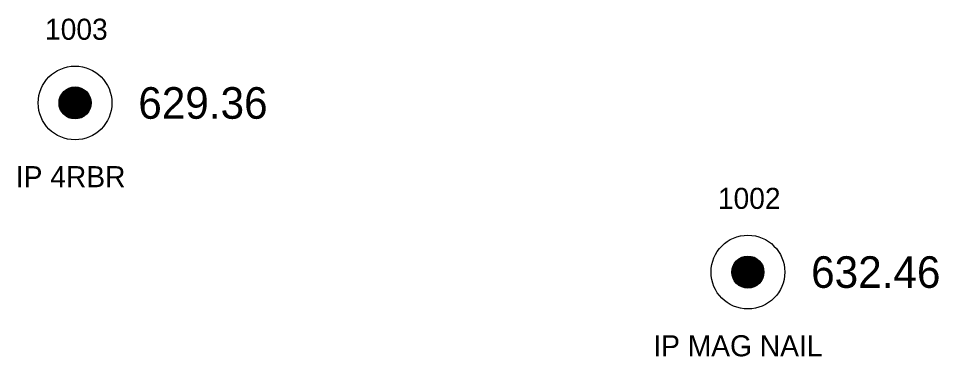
# Model space of a CAD drawing. Extents: x 1694813 to 1696862, y 1086485 to 1091027.
# Drawn here: x 1695770.52 to 1695814.17, y 1087216.3 to 1087232.36 of the extents above; entities that cross this region are included whole.
import ezdxf

# ---------------------------------------------------------------- set-up
doc = ezdxf.new("R2010")
doc.units = 0
for name, color, linetype in [('RD_EX_DV_Prop_txCode', 7, 'Continuous'), ('RD_EX_DV_PropPin', 7, 'Continuous'), ('RD_EX_TX_DV_Prop_ELEV', 7, 'Continuous'), ('RD_SMD_Locator', 7, 'Continuous')]:
    doc.layers.add(name, color=color, linetype=linetype)

msp = doc.modelspace()

# ---------------------------------------------------------------- linework, layer by layer
at = {"layer": 'RD_EX_DV_PropPin'}
for p, q in [((1695772.715, 1087227.762), (1695772.715, 1087228.927)), ((1695772.75, 1087227.735), (1695772.75, 1087228.954)), ((1695772.785, 1087227.71), (1695772.785, 1087228.979)), ((1695772.82, 1087227.688), (1695772.82, 1087229.001)), ((1695772.855, 1087227.669), (1695772.855, 1087229.02)), ((1695772.89, 1087227.652), (1695772.89, 1087229.037)), ((1695772.925, 1087227.637), (1695772.925, 1087229.052)), ((1695772.96, 1087227.624), (1695772.96, 1087229.065)), ((1695772.995, 1087227.613), (1695772.995, 1087229.076)), ((1695773.03, 1087227.604), (1695773.03, 1087229.085)), ((1695773.065, 1087227.596), (1695773.065, 1087229.093)), ((1695773.1, 1087227.591), (1695773.1, 1087229.098)), ((1695773.135, 1087227.587), (1695773.135, 1087229.102)), ((1695773.17, 1087227.584), (1695773.17, 1087229.105)), ((1695773.205, 1087227.583), (1695773.205, 1087229.106)), ((1695773.24, 1087227.584), (1695773.24, 1087229.105)), ((1695773.275, 1087227.587), (1695773.275, 1087229.102)), ((1695773.31, 1087227.591), (1695773.31, 1087229.098)), ((1695773.345, 1087227.596), (1695773.345, 1087229.093)), ((1695773.38, 1087227.604), (1695773.38, 1087229.085)), ((1695773.415, 1087227.613), (1695773.415, 1087229.076)), ((1695773.45, 1087227.624), (1695773.45, 1087229.065)), ((1695773.485, 1087227.637), (1695773.485, 1087229.052)), ((1695773.52, 1087227.652), (1695773.52, 1087229.037)), ((1695773.555, 1087227.669), (1695773.555, 1087229.02)), ((1695773.59, 1087227.688), (1695773.59, 1087229.001)), ((1695773.625, 1087227.71), (1695773.625, 1087228.979)), ((1695773.66, 1087227.735), (1695773.66, 1087228.954)), ((1695773.695, 1087227.762), (1695773.695, 1087228.927)), ((1695772.47, 1087228.148), (1695772.47, 1087228.541)), ((1695772.505, 1087228.047), (1695772.505, 1087228.642)), ((1695772.54, 1087227.975), (1695772.54, 1087228.714)), ((1695772.575, 1087227.918), (1695772.575, 1087228.771)), ((1695772.61, 1087227.87), (1695772.61, 1087228.819)), ((1695772.645, 1087227.829), (1695772.645, 1087228.86)), ((1695772.68, 1087227.794), (1695772.68, 1087228.895)), ((1695773.73, 1087227.794), (1695773.73, 1087228.895)), ((1695773.766, 1087227.829), (1695773.766, 1087228.86)), ((1695773.801, 1087227.87), (1695773.801, 1087228.819)), ((1695773.836, 1087227.918), (1695773.836, 1087228.771)), ((1695773.871, 1087227.975), (1695773.871, 1087228.714)), ((1695773.906, 1087228.047), (1695773.906, 1087228.642)), ((1695773.941, 1087228.148), (1695773.941, 1087228.541)), ((1695804.953, 1087219.575), (1695804.953, 1087221.056)), ((1695804.988, 1087219.567), (1695804.988, 1087221.063)), ((1695805.023, 1087219.562), (1695805.023, 1087221.069)), ((1695805.058, 1087219.558), (1695805.058, 1087221.073)), ((1695805.093, 1087219.555), (1695805.093, 1087221.076)), ((1695805.128, 1087219.554), (1695805.128, 1087221.076)), ((1695805.163, 1087219.555), (1695805.163, 1087221.076)), ((1695805.198, 1087219.558), (1695805.198, 1087221.073)), ((1695805.233, 1087219.562), (1695805.233, 1087221.069)), ((1695805.268, 1087219.567), (1695805.268, 1087221.063)), ((1695805.303, 1087219.575), (1695805.303, 1087221.056)), ((1695804.427, 1087220.017), (1695804.427, 1087220.613)), ((1695804.463, 1087219.946), (1695804.463, 1087220.685)), ((1695804.498, 1087219.889), (1695804.498, 1087220.742)), ((1695804.533, 1087219.841), (1695804.533, 1087220.789)), ((1695804.568, 1087219.8), (1695804.568, 1087220.83)), ((1695804.603, 1087219.765), (1695804.603, 1087220.866)), ((1695804.638, 1087219.733), (1695804.638, 1087220.897)), ((1695804.673, 1087219.705), (1695804.673, 1087220.925)), ((1695804.708, 1087219.681), (1695804.708, 1087220.95)), ((1695804.743, 1087219.659), (1695804.743, 1087220.972)), ((1695804.778, 1087219.64), (1695804.778, 1087220.991)), ((1695804.813, 1087219.623), (1695804.813, 1087221.008)), ((1695804.848, 1087219.608), (1695804.848, 1087221.023)), ((1695804.883, 1087219.595), (1695804.883, 1087221.036)), ((1695804.918, 1087219.584), (1695804.918, 1087221.047)), ((1695805.338, 1087219.584), (1695805.338, 1087221.047)), ((1695805.373, 1087219.595), (1695805.373, 1087221.036)), ((1695805.408, 1087219.608), (1695805.408, 1087221.023)), ((1695805.443, 1087219.623), (1695805.443, 1087221.008)), ((1695805.478, 1087219.64), (1695805.478, 1087220.991)), ((1695805.513, 1087219.659), (1695805.513, 1087220.972)), ((1695805.548, 1087219.681), (1695805.548, 1087220.95)), ((1695805.583, 1087219.705), (1695805.583, 1087220.925)), ((1695805.618, 1087219.733), (1695805.618, 1087220.897)), ((1695805.653, 1087219.765), (1695805.653, 1087220.866)), ((1695805.688, 1087219.8), (1695805.688, 1087220.83)), ((1695805.723, 1087219.841), (1695805.723, 1087220.789)), ((1695805.758, 1087219.889), (1695805.758, 1087220.742)), ((1695805.793, 1087219.946), (1695805.793, 1087220.685)), ((1695805.828, 1087220.017), (1695805.828, 1087220.613)), ((1695804.392, 1087220.119), (1695804.392, 1087220.511)), ((1695805.863, 1087220.119), (1695805.863, 1087220.511))]:
    msp.add_line(p, q, dxfattribs=at)
for centre, radius in [((1695773.205, 1087228.344), 1.75), ((1695773.205, 1087228.344), 0.761), ((1695805.128, 1087220.315), 1.75), ((1695805.128, 1087220.315), 0.761)]:
    msp.add_circle(centre, radius, dxfattribs=at)
at = {"layer": 'RD_SMD_Locator'}
for centre in [(1695773.205, 1087228.344), (1695805.128, 1087220.315)]:
    msp.add_circle(centre, 0.15, dxfattribs=at)

# ---------------------------------------------------------------- texts
at = {"layer": 'RD_EX_DV_Prop_txCode'}
for s, p in [('1003', (1695771.78, 1087231.344)), ('IP 4RBR', (1695770.394, 1087224.344)), ('1002', (1695803.703, 1087223.315)), ('IP MAG NAIL', (1695800.64, 1087216.315))]:
    msp.add_text(s, height=1, dxfattribs=at).set_placement(p)
at = {"layer": 'RD_EX_TX_DV_Prop_ELEV'}
for s, p in [('629.36', (1695776.205, 1087227.594)), ('632.46', (1695808.128, 1087219.565))]:
    msp.add_text(s, height=1.5, dxfattribs=at).set_placement(p)

doc.saveas('drawing.dxf')
